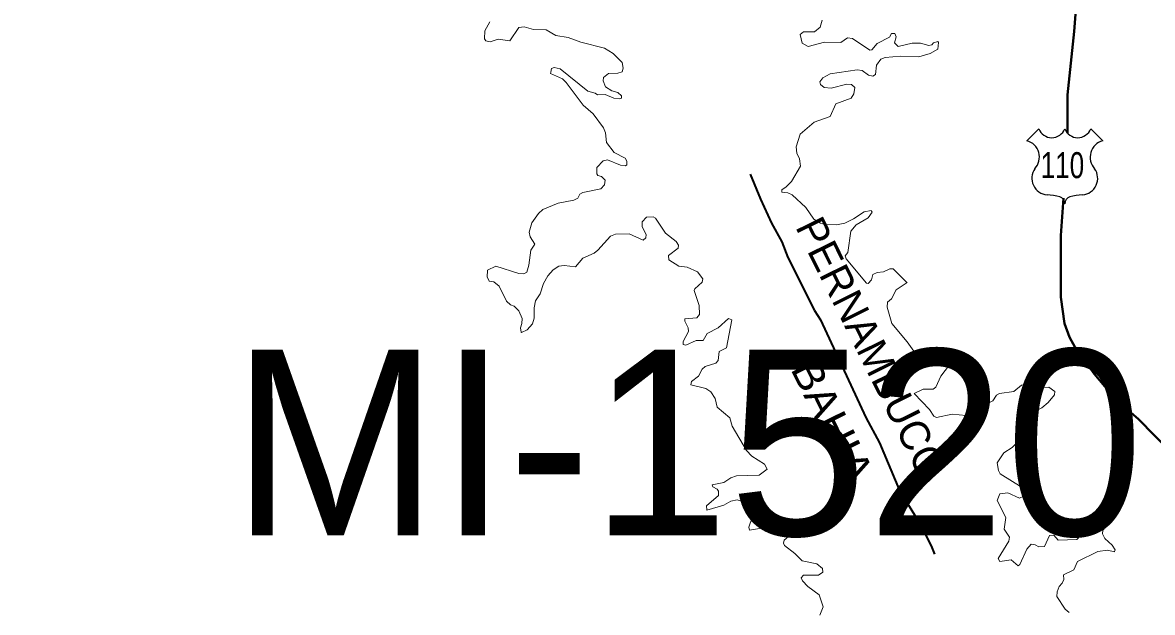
# Model space of a CAD drawing. Extents: x -1643653 to 4543381, y 1624270 to 13878484.
# Drawn here: x 577543 to 580582, y 8914739 to 8916326 of the extents above; entities that cross this region are included whole.
import ezdxf
from ezdxf.enums import TextEntityAlignment as Align

# ---------------------------------------------------------------- set-up
doc = ezdxf.new("R2010")
doc.units = 0
doc.header["$LTSCALE"] = 160
doc.linetypes.add('LONG_DASH_SHORT_DASH', pattern=[9.9, 6, -1.2, 1.5, -1.2])
doc.layers.add('6', color=7, linetype='Continuous', lineweight=13)
doc.layers.add('60', color=7, linetype='Continuous', lineweight=13)

msp = doc.modelspace()

# ---------------------------------------------------------------- linework, layer by layer
at = {"layer": '6', "lineweight": 25}
for p, q in [((580244.9, 8916008.7), (580276.8, 8916040.7)), ((580416.7, 8916040.7), (580448.7, 8916008.7))]:
    msp.add_line(p, q, dxfattribs=at)
at = {"layer": '6', "lineweight": 40}
for points in [[(579213.9, 8917803.6), (579228.4, 8917763.4), (579242.2, 8917742.7), (579298.8, 8917690.5), (579364.6, 8917617.7), (579396.1, 8917591.3), (579545.7, 8917448.6), (579623.5, 8917387.3), (579718.5, 8917299.9), (579761.2, 8917250.1), (579934.8, 8917073.4), (579974.1, 8917041), (580094.4, 8916919), (580138.8, 8916860.8), (580185.2, 8916812.2), (580237.9, 8916747.8), (580356.4, 8916554.1), (580378.4, 8916492), (580386.2, 8916445.1), (580380.2, 8916408), (580372.4, 8916302.5), (580354.2, 8916132.1), (580354.2, 8916028.7)], [(580343.7, 8915853.7), (580336.1, 8915753.4), (580336.5, 8915587.3), (580346.4, 8915516.3), (580359, 8915480.1), (580374.6, 8915452.4), (580426, 8915381.5), (580483.5, 8915313.2), (580544.8, 8915258.9), (580632.4, 8915170.4), (580707.5, 8915102.2), (580796.1, 8915008), (580864.8, 8914944.9), (580908, 8914896.5), (580975.6, 8914807.3), (581014.1, 8914768.8), (581054.2, 8914715.7)]]:
    msp.add_lwpolyline(points, dxfattribs=at)
at = {"layer": '6'}
for points in [[(578800.4, 8916328.4), (578786.4, 8916304), (578785.6, 8916283.2), (578789, 8916277.3), (578801.2, 8916274.7), (578822.6, 8916281.5), (578853.9, 8916277.3), (578878.1, 8916312.9), (578892.2, 8916315.5), (578917.7, 8916308.3), (578951.5, 8916307), (578977.3, 8916292.1), (579011.2, 8916286.2), (579045.2, 8916273.5), (579108.9, 8916257.3), (579132.3, 8916243.2), (579156.4, 8916219.1), (579159, 8916203.8), (579156.4, 8916194.4), (579144.6, 8916190.6), (579119, 8916189.3), (579105.6, 8916178.4), (579104.6, 8916169.8), (579111.2, 8916153.5), (579128.1, 8916142.5), (579144.1, 8916137.9), (579154.2, 8916129.1), (579153.9, 8916123.1), (579148.8, 8916120.9), (579133.4, 8916123.1), (579110.6, 8916132.8), (579089.3, 8916132), (579083.8, 8916136.7), (579063.8, 8916142.2), (578989, 8916201.7), (578972.9, 8916205.2), (578965.6, 8916203.3), (578963.8, 8916193.1)], [(580007.4, 8916273.3), (580005, 8916275.8), (579993.4, 8916271.9), (579988.7, 8916266.2), (579980.8, 8916265), (579958.6, 8916271.3), (579936.5, 8916271.3), (579898.3, 8916262), (579888.5, 8916271.8), (579893.2, 8916288), (579889.2, 8916296.8), (579880.4, 8916297.2), (579874.8, 8916287), (579841.8, 8916270.1), (579827.8, 8916253.1), (579822.2, 8916252.2), (579776.1, 8916284.1), (579776.1, 8916284.1), (579761.9, 8916285.8), (579744.5, 8916273.1), (579700.5, 8916273.9), (579656.1, 8916262.4), (579640, 8916271.3), (579634.5, 8916294.7), (579643.7, 8916301.5), (579673.1, 8916301.5), (579688.3, 8916313.8), (579694.3, 8916332.9)], [(579827, 8915819.2), (579826.3, 8915820.9), (579806.9, 8915817.1), (579778.4, 8915798), (579755.5, 8915787), (579732.5, 8915781.9), (579702, 8915783.2), (579689.3, 8915787), (579671.8, 8915797.6), (579650.6, 8915829.1), (579613.6, 8915863), (579601.7, 8915868.1), (579586, 8915869.9), (579586, 8915876.6), (579597.1, 8915884.3), (579611.5, 8915898.7), (579635.7, 8915940.4), (579632.8, 8915960), (579625.5, 8915975.2), (579623.8, 8915992.2), (579634.5, 8916026.2), (579673, 8916058.4), (579715.6, 8916073.8), (579731.3, 8916108.2), (579772.1, 8916123.5), (579779.7, 8916134.4), (579781.8, 8916151.9), (579772.9, 8916160), (579760.6, 8916160.9), (579718.1, 8916149.8), (579699.4, 8916151.6), (579689.2, 8916160), (579688, 8916167.1), (579696, 8916177.8), (579715.7, 8916188.6), (579788.6, 8916199.5), (579801.3, 8916197.8), (579818.4, 8916184.7), (579830.3, 8916182.6), (579837.5, 8916186.4), (579840.1, 8916212.3), (579852, 8916228), (579863.6, 8916232.3), (579905.1, 8916236.1), (579954.3, 8916233.9), (579985, 8916242.9), (580004.9, 8916254.8), (580007.4, 8916273.3)], [(578963.8, 8916193.1), (578963.2, 8916189.9), (578995.4, 8916174.9), (579005.6, 8916165.6), (579051.5, 8916104), (579078.2, 8916080.6), (579106.3, 8916043.6), (579111.4, 8916029.6), (579114, 8916004.1), (579134.4, 8915976.5), (579163.8, 8915961.6), (579168.8, 8915953.1), (579168.3, 8915943.7), (579165.3, 8915940.8), (579151.4, 8915942.5), (579116.9, 8915956.9), (579104.6, 8915954.4), (579087.6, 8915936.9), (579088.1, 8915919.4), (579091, 8915915.3), (579100.5, 8915912.6), (579110.1, 8915902.1), (579108.9, 8915889.4), (579108.9, 8915889.4), (579099.1, 8915878.8), (579050.3, 8915869), (579042.6, 8915864.7), (579036.6, 8915854.1), (579026.5, 8915848.6), (578984, 8915840.1), (578942.8, 8915823.6), (578931.3, 8915812.9), (578913.5, 8915787.4), (578906.3, 8915762.8), (578908.8, 8915749.6), (578920.7, 8915730.2), (578910.1, 8915714.3), (578905.4, 8915673.6), (578899.8, 8915654.9), (578891.3, 8915650.6), (578877.8, 8915651.1), (578816.4, 8915671), (578794.2, 8915660.6)], [(579921.2, 8915628.2), (579885.3, 8915664.2), (579876.2, 8915663.8), (579859.2, 8915655.3), (579842.2, 8915653.6), (579830.8, 8915648.5), (579826.8, 8915634.3), (579817.6, 8915624.4), (579813.3, 8915625.1), (579758.5, 8915690.5), (579756.4, 8915699.1), (579762.7, 8915707.9), (579770.8, 8915765.3), (579785.7, 8915781.9), (579817.5, 8915801), (579828.2, 8915816.6), (579827, 8915819.2)], [(578884.8, 8915493.7), (578885.1, 8915492.2), (578900.5, 8915499.9), (578915, 8915515.8), (578919.4, 8915530.8), (578919, 8915558.8), (578922.8, 8915577.5), (578935.5, 8915596.2), (578944.9, 8915624.3), (578956.3, 8915644.6), (578970.4, 8915660.8), (578985.6, 8915671), (579000.1, 8915672.7), (579030.7, 8915669.3), (579050.3, 8915692.7), (579080.5, 8915706.3), (579090.6, 8915713.9), (579124.6, 8915752.1), (579137.7, 8915756.8), (579175.2, 8915757.7), (579212.6, 8915741.2), (579219.7, 8915747), (579221, 8915756.1), (579209.6, 8915777.2), (579210, 8915789.9), (579221.2, 8915802.8), (579239.2, 8915804), (579245.7, 8915800.2), (579272.9, 8915759.8), (579300.9, 8915737.7), (579307.3, 8915727.1), (579306.8, 8915719.5), (579280.5, 8915699.9), (579281.8, 8915688), (579308.6, 8915671), (579330.7, 8915668), (579358.8, 8915655.6), (579373.5, 8915637), (579371.4, 8915628.1), (579351.5, 8915609.8), (579350.2, 8915605.2), (579362.9, 8915564.8), (579364.2, 8915540.6), (579356.9, 8915531.6), (579325, 8915529.4), (579324.7, 8915523.2), (579333.3, 8915505.4), (579334.9, 8915495.1), (579320.1, 8915467.9), (579320.5, 8915460.3), (579327.3, 8915458.6), (579355.3, 8915470.5), (579373.6, 8915470.5), (579385.1, 8915489.7), (579414.3, 8915505.3), (579442.3, 8915530.3), (579450.8, 8915526.1), (579436.8, 8915451.4), (579417.3, 8915441.1), (579414.3, 8915417.4), (579407.7, 8915410.3), (579379.6, 8915400.8), (579371.1, 8915394), (579361.2, 8915375.3), (579342.8, 8915360.6), (579340.4, 8915351.5), (579381.5, 8915341.8), (579394.8, 8915332.4), (579405.9, 8915314.9), (579411.8, 8915291.1), (579445.3, 8915262.8), (579445.3, 8915262.8), (579452.2, 8915240.7), (579490.9, 8915175.1), (579504.9, 8915159.9), (579538.8, 8915137.8), (579546.4, 8915124.3), (579524.3, 8915108.1), (579464, 8915106.8), (579448.3, 8915101.7), (579429.2, 8915089), (579398.2, 8915082.2), (579399.9, 8915077.5), (579411.4, 8915071.1), (579415.2, 8915065.2), (579415.2, 8915053.8), (579383.3, 8915026.2), (579384.2, 8915014.9)], [(578794.2, 8915660.6), (578793.2, 8915641.7), (578798.1, 8915631.8)], [(578798.1, 8915631.8), (578798.6, 8915630.9), (578810.7, 8915628.9), (578825.5, 8915617.1), (578845.1, 8915577.1), (578856.1, 8915567), (578865.9, 8915563), (578878.2, 8915550.3), (578887.1, 8915529.8), (578886.5, 8915516.3), (578882.2, 8915504.7), (578884.8, 8915493.7)], [(580319.7, 8915333.8), (580319.7, 8915334.1), (580303.4, 8915345.2), (580265, 8915344.8), (580242.4, 8915351.9), (580230.5, 8915351.1), (580209.3, 8915334.1), (580171.4, 8915328.2), (580163.5, 8915323.6), (580153.6, 8915308.2), (580123.4, 8915293.3), (580116.2, 8915278.5), (580104.8, 8915272.5), (580081.8, 8915268.7), (580043.5, 8915272.5), (580002, 8915263.6), (579994.3, 8915267), (579994.3, 8915267), (579982.4, 8915285.2), (579941.6, 8915328.6), (579966.2, 8915339.6), (579992.4, 8915339.6), (580000.2, 8915345.2), (580013.4, 8915374.5), (580036.8, 8915405.1), (580058.9, 8915413.2), (580063.1, 8915419.8), (580062.2, 8915424.6), (580045.2, 8915432.7), (580022.3, 8915423.4), (579998.1, 8915429.3), (579962.9, 8915419.5), (579949.7, 8915429.2), (579922.5, 8915467.5), (579881.7, 8915516.3), (579868.5, 8915560.6), (579869.8, 8915574.1), (579880.9, 8915582.8), (579893.2, 8915607.7), (579922.7, 8915626.6), (579921.2, 8915628.2)], [(580480.8, 8914902.8), (580482.1, 8914907.6), (580474.3, 8914920.3), (580454.4, 8914937.7), (580448, 8914950.4), (580448.9, 8914960.2), (580457.3, 8914969.6), (580462.4, 8914982.3), (580461.6, 8914992.9), (580454.3, 8914999.7), (580438.2, 8914993.8), (580417, 8914976.4), (580378.8, 8914935.2), (580328.7, 8914933.9), (580317.1, 8914946.6), (580305.5, 8914945.8), (580292, 8914916.9), (580276.5, 8914915.2), (580267, 8914921.1), (580255.9, 8914922.4), (580244.5, 8914909.3), (580225.8, 8914868.5), (580221.2, 8914864.7), (580202.9, 8914880.3), (580172.3, 8914875.7), (580167.2, 8914884.2), (580196.5, 8914930.9), (580198.2, 8914941.9), (580183.3, 8914963.2), (580188, 8914995), (580165.1, 8915040.5), (580171.9, 8915057.9), (580193.5, 8915060.9), (580224.5, 8915046.9), (580236.8, 8915052.4), (580238.5, 8915059.3), (580231.8, 8915074.9), (580173.1, 8915112.3), (580168, 8915121.3), (580164.7, 8915141.3), (580182.9, 8915168.8), (580205, 8915183.3), (580217.7, 8915195.6), (580223.7, 8915213), (580225.4, 8915235.1), (580231.8, 8915246.2), (580262.3, 8915278.4), (580284.9, 8915290), (580302.2, 8915303.9), (580318.7, 8915324.9), (580319.7, 8915333.8)], [(579384.2, 8915014.9), (579384.2, 8915014.7), (579429.2, 8915027.4), (579448, 8915038.8), (579465.7, 8915042.2), (579504.8, 8915030.8), (579515, 8915020.6), (579496.4, 8914968.3), (579498.8, 8914960.3), (579525.3, 8914964.9), (579586.4, 8914984), (579600.8, 8914979.4), (579609.8, 8914967.5), (579609.3, 8914948.3), (579591.5, 8914933.5), (579589.8, 8914925.9), (579593.2, 8914919.1), (579620.8, 8914897.8), (579640, 8914878.3), (579679.4, 8914870.2), (579695.2, 8914857.4), (579696, 8914847.2), (579684.5, 8914839.8), (579644.2, 8914839.6), (579637.8, 8914832.4), (579640.8, 8914823.8), (579655.7, 8914808.6), (579686.2, 8914786.1), (579696.4, 8914754.2), (579687.9, 8914732.1)], [(580358.4, 8914738.5), (580348.2, 8914748.2), (580325.2, 8914781.9), (580326.1, 8914794.1), (580332, 8914809.3), (580340.1, 8914817.9), (580343.9, 8914827.7), (580343.5, 8914840), (580371.1, 8914854), (580380.9, 8914876.1), (580436.1, 8914903.3), (580461.9, 8914906.3), (580480.7, 8914902.3), (580480.8, 8914902.8)]]:
    msp.add_lwpolyline(points, dxfattribs=at)
at = {"layer": '6', "linetype": 'LONG_DASH_SHORT_DASH', "lineweight": 35}
msp.add_lwpolyline([(579500.5, 8915918.8), (579528, 8915851.1), (579557.9, 8915787.1), (579585.9, 8915736.1), (579601.5, 8915694.6), (579673.2, 8915551.9), (579689.7, 8915526.8), (579811.6, 8915263.9), (579848.4, 8915195.6), (579902.4, 8915066.8), (579956.9, 8914978.6), (579987.7, 8914917.9), (579996, 8914895.7)], dxfattribs=at)
at = {"layer": '6', "lineweight": 25}
for centre, radius, start, end in [((580311.8, 8916054.1), 37.4, 200.9593, 339.0407), ((580381.7, 8916054.1), 37.4, 200.9593, 339.0407), ((580232.4, 8915964.3), 46.1, 317.5721, 74.3689), ((580461.1, 8915964.3), 46.1, 105.6277, 222.4279), ((580303.1, 8915907.3), 44.9, 144.7373, 264.6578), ((580390.4, 8915907.3), 44.9, 275.3422, 35.2627), ((580298.8, 8915744.6), 118, 72.8937, 89.9006), ((580327.9, 8915839.3), 18.9, 357.6934, 72.9296), ((580365.7, 8915839.3), 18.9, 107.0704, 182.3065), ((580394.8, 8915744.6), 118, 90.0994, 107.1063)]:
    msp.add_arc(centre, radius, start, end, dxfattribs=at)
at = {"layer": '60', "lineweight": 25}
msp.add_spline([(814781, 9009175.5), (814787.2, 9009173.4), (814796.9, 9009173.4), (814799.4, 9009172.4), (814805.1, 9009174.5), (814805.6, 9009176.5), (814811.7, 9009179.5), (814811.7, 9009179.5), (814801.5, 9009181), (814790.7, 9009181.5), (814784.1, 9009183.1), (814777.4, 9009185.1), (814778.4, 9009175.5)], degree=3, dxfattribs=at)

# ---------------------------------------------------------------- texts
at = {"layer": '6', "width": 0.75}
msp.add_text('110', height=70, dxfattribs=at).set_placement((580340.4, 8915907.8), align=Align.CENTER)
at = {"layer": '6'}
msp.add_text('PERNAMBUCO', height=80, rotation=296.367, dxfattribs=at).set_placement((579791, 8915433.4), align=Align.CENTER)
msp.add_text('MI-1520', height=500, dxfattribs=at).set_placement((578105.8, 8914946.5))
at = {"layer": '6', "width": 1.1}
msp.add_text('BAHIA', height=80, rotation=296.367, dxfattribs=at).set_placement((579686.1, 8915236.7), align=Align.CENTER)

doc.saveas('drawing.dxf')
